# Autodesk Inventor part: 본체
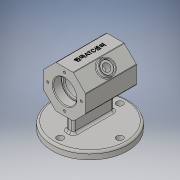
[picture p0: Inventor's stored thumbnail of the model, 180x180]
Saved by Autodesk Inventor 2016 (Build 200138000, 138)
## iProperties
Created: 2021-02
Part Number: 본체
Material: 일반
Document SubType Name: Modeling
Designer: WIN7
Density: 1 g/cm^3
Appearance: 기본값
Author: WIN7
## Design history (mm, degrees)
sketch "스케치1"
  geometry: L1 (40.6, 0)-(-40.6, 0) reference; L2 (0, -40.6)-(0, 40.6) reference; L3 (12.012, 29)-(29, 12.012); L4 (29, 12.012)-(29, -12.012); L5 (29, -12.012)-(12.012, -29); L6 (12.012, -29)-(-12.012, -29); L7 (-12.012, -29)-(-29, -12.012); L8 (-29, -12.012)-(-29, 12.012); L9 (-29, 12.012)-(-12.012, 29); L10 (-12.012, 29)-(12.012, 29); C1 r 29 at (0, 0); 3 further points
  constraints: 16 end point, 2 coincident, 1 centre point, 1 midpoint, 1 point on line, 1 tangent, 17 other
  dimensions: "d0" = 58 diameter of C1
extrude "돌출1" new body sketch "스케치1" stored distance "d1" = 70; taper "d2" = 0 deg
sketch "스케치2"
  geometry: L1 (-49, 0)-(49, 0) reference; L2 (0, -40.6)-(0, 40.6) reference; L3 (-35, 0)-(-35, 16); L4 (-35, 16)-(-23, 16); L5 (-35, 29)-(-35, 12.012) reference; L6 (-23, 16)-(-23, 14); L7 (-23, 14)-(-20, 14); L8 (-20, 14)-(-20, 22); L9 (-20, 22)-(0, 22); L10 (0, 22)-(0, 0); L11 (0, 0)-(-35, 0); L12 (-35, 12.012)-(-35, -12.012) reference; L13 (20, 22)-(0, 22); L14 (20, 14)-(20, 22); L15 (23, 14)-(20, 14); L16 (23, 16)-(23, 14); L17 (35, 16)-(23, 16); L18 (35, 0)-(35, 16); L19 (0, 0)-(35, 0)
  constraints: 30 end point, 6 perpendicular, 6 symmetric about line, 3 point on line, 1 collinear, 1 vertical
  dimensions: "d3" = 20 distance between parallel lines of L2 L8; "d4" = 12 distance between parallel lines of L3 L6; "d5" = 22 distance between parallel lines of L1 L9; "d6" = 14 distance between parallel lines of L1 L7; "d7" = 16 distance between parallel lines of L1 L4
revolve "회전1" sketch "스케치2" stored, may be unused: angle "d8" = 90 deg
node "작업 평면1"
sketch "스케치3"
  geometry: L1 (5, 28)-(-5, 28); L2 (-5, 28)-(-5, -28); L3 (-5, -28)-(5, -28); L4 (5, -28)-(5, 28); L5 (5, 28)-(-5, -28); L6 (-5, 28)-(5, -28); C1 r 52 at (0, 0); 1 further point
  constraints: 12 end point, 2 midpoint, 2 parallel, 1 centre point, 1 coincident, 1 horizontal, 1 perpendicular
  dimensions: "d10" = 104 diameter of C1; "d11" = 10 distance of L3.end L2.end; "d12" = 56 distance of L2.end L1.end
extrude "돌출2" join sketch "스케치3" stored distance "d13" = 70; taper "d14" = 0 deg
extrude "돌출3" join sketch "스케치3" distance "d15" = 10; taper "d16" = 0 deg
sketch "스케치4"
  geometry: L1 (0, 0)-(-41, 0)
  constraints: 2 end point, 1 horizontal
  dimensions: "d17" = 41 distance of L1.start L1.end
hole "구멍1" sketch "스케치4" at (-41, 0) diameter "d18" = 9; stored, may be unused: countersink angle "d22" = 90 deg, drill point angle "d24" = 118 deg; dims "d19" = 6, "d20" = 4, "d21" = 2, "d23" = 8
node "작업 평면2"
sketch "스케치5"
  geometry: C1 r 10 at (-12.012, 35); 1 further point
  constraints: 1 centre point, 1 coincident
  dimensions: "d29" = 20 diameter of C1
extrude "돌출4" join sketch "스케치5" stored distance "d30" = 10; taper "d31" = 0 deg
sketch "스케치6"
  geometry: 1 further point
hole "구멍2" sketch "스케치6" at (-12.012, 35) diameter "d32" = 10.106; stored, may be unused: countersink angle "d36" = 90 deg, drill point angle "d38" = 118 deg; dims "d33" = 24, "d34" = 16, "d35" = 2, "d37" = 32.3
node "작업 평면3"
sketch "스케치7"
  geometry: L1 (-72.47, -35)-(86.759, -35) reference; 1 further point
  constraints: 1 other
feature "엠보싱1" sketch "스케치7" dims "d40" = 0.5, "d41" = 0
node "작업 평면4"
sketch "스케치8"
  geometry: L1 (0, 0)-(0, 23)
  constraints: 2 end point, 1 vertical
  dimensions: "d43" = 23 distance of L1.start L1.end
hole "구멍3" sketch "스케치8" at (0, 23) diameter "d44" = 3.242; stored, may be unused: countersink angle "d48" = 90 deg, drill point angle "d50" = 118 deg; dims "d45" = 8, "d46" = 16, "d47" = 2, "d49" = 10
fillet "모깎기1" dims "d54" = 1
fillet "모깎기2" dims "d55" = 0.3
fillet "모깎기3" dims "d56" = 3
chamfer "모따기1" distance "d57" = 1; stored, may be unused: second distance "d58" = 2, angle "d59" = 45 deg
fillet "모깎기4" dims "d60" = 3
chamfer "모따기2" distance "d61" = 1; stored, may be unused: second distance "d62" = 2, angle "d63" = 45 deg
fillet "모깎기5" dims "d64" = 3
fillet "모깎기6" dims "d66" = 1
node "작업 평면5"
feature "분할1"
node "솔리드1"
pattern_circular "원형 패턴1" dims angle "d26" = 360 deg
pattern_circular "원형 패턴2" dims angle "d52" = 360 deg
mirror "대칭1"
other parameters: "d9" = -62, "d28" = 5, "d39" = 5, "d42" = 0, "d65" = 0
